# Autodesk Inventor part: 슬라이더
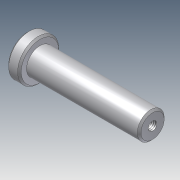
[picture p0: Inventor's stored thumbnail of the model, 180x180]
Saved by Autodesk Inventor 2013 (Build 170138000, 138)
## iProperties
Company: 한국ATC센터
Created: 2014-08
Part Number: 슬라이더
Document SubType Name: Modeling
Designer: KYOUNG IL JANG
Density: 1 g/cm^3
Material: 일반
Mass: 13.6925 g
Surface Area: 43.9337 cm^2
Volume: 13.6925 cm^3
Author: KYOUNG IL JANG
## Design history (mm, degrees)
sketch "스케치1"
  geometry: L1 (-7, 0)-(63, 0); L2 (63, 0)-(63, 7.5); L3 (63, 7.5)-(0, 7.5); L4 (-7, 0)-(-7, 11.5); L5 (-7, 11.5)-(0, 11.5); L6 (0, 11.5)-(0, 7.5); 1 further point
  constraints: 12 end point, 3 perpendicular, 2 horizontal, 2 point on line, 1 parallel
  dimensions: "d1" = 70 distance of L1.start L1.end; "d19" = 15 diameter of L3 L1; "d20" = 7 distance of L4.end L5.end; "d21" = 23 diameter of L5 L1
revolve "회전1" stored, may be unused: angle "d4" = 90 deg
chamfer "모따기1" distance "d16" = 1; stored, may be unused: second distance "d17" = 2, angle "d18" = 45 deg
hole "구멍2" diameter "d24" = 4.917; stored, may be unused: countersink angle "d28" = 90 deg, drill point angle "d30" = 118 deg; dims "d22" = 10, "d23" = 10, "d25" = 10, "d26" = 4, "d27" = 2, "d29" = 13
node "솔리드1"
